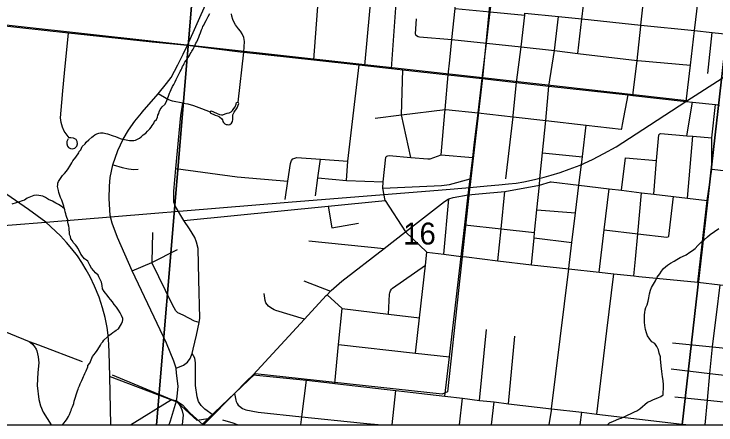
# Model space of a CAD drawing. Extents: x 0 to 34, y -3.9 to 26.2.
# Drawn here: x 5.335 to 6.675, y 14.1 to 14.885 of the extents above; entities that cross this region are included whole.
import ezdxf

# ---------------------------------------------------------------- set-up
doc = ezdxf.new("R2010")
doc.units = 0
for name, color, linetype in [('GM_X_City_Street', 7, 'Continuous'), ('GM_X_County_Road', 7, 'Continuous'), ('GM_X_Interchange_Ramps', 7, 'Continuous'), ('GM_X_Interstate_Route', 7, 'Continuous'), ('GM_X_Minor_River', 7, 'Continuous'), ('GM_X_Rail_Line', 7, 'Continuous'), ('GM_X_Section_Text', 7, 'Continuous'), ('GM_X_State_Shield', 7, 'Continuous'), ('GM_X_Township_Road', 7, 'Continuous')]:
    doc.layers.add(name, color=color, linetype=linetype)

msp = doc.modelspace()

# ---------------------------------------------------------------- linework, layer by layer
at = {"layer": 'GM_X_City_Street'}
for p, q in [((5.907, 14.7972), (5.9228, 15.002)), ((6.6592, 14.7711), (6.6674, 14.8497)), ((5.7629, 14.7169), (5.7738, 14.8119)), ((6.6189, 14.6524), (6.6302, 14.7168)), ((6.6202, 14.5332), (6.6307, 14.6515)), ((6.3437, 14.62), (6.4197, 14.612)), ((6.4946, 14.5483), (6.5021, 14.6104)), ((6.5021, 14.6104), (6.5613, 14.6049)), ((6.1551, 14.4261), (6.1651, 14.5317)), ((5.9343, 14.5181), (5.9418, 14.4763)), ((6.3329, 14.5108), (6.4067, 14.5054)), ((5.9418, 14.4763), (5.9922, 14.4856)), ((6.3276, 14.4576), (6.3998, 14.4486)), ((5.8976, 14.452), (6.0415, 14.4373)), ((5.8881, 14.3755), (5.939, 14.3554)), ((6.2233, 14.147), (6.2369, 14.2823)), ((6.2784, 14.1406), (6.2908, 14.2694)), ((5.6748, 14.2366), (5.6767, 14.2446)), ((6.0567, 14.1), (6.0636, 14.1661)), ((5.5575, 14.1), (5.6352, 14.1489)), ((6.1854, 14.1), (6.1912, 14.1514)), ((6.4153, 14.1), (6.4185, 14.1246)), ((6.6098, 14.1), (6.61, 14.1017))]:
    msp.add_line(p, q, dxfattribs=at)
for points in [[(6.15, 14.6163), (6.1575, 14.6966), (6.1581, 14.7026), (6.1635, 14.7688), (6.167, 14.797), (6.1707, 14.8362), (6.1767, 14.8958), (6.1769, 14.8976), (6.184, 14.968), (6.1848, 14.9759), (6.1993, 15.1189), (6.2028, 15.1537), (6.2075, 15.1994)], [(6.4111, 14.8098), (6.4188, 14.8758), (6.4194, 14.8804), (6.4271, 14.947), (6.4333, 15.0223), (6.4383, 15.083)], [(6.0554, 14.7812), (6.0641, 14.9056), (6.0652, 14.9071), (6.0667, 14.9078), (6.0698, 14.9081), (6.0804, 14.9086), (6.0825, 14.909), (6.0838, 14.9101), (6.0846, 14.9112), (6.0851, 14.9138), (6.094, 14.9866), (6.0979, 15.0186), (6.1013, 15.0467)], [(6.5161, 14.7291), (6.5244, 14.7965), (6.5312, 14.8617), (6.5315, 14.864), (6.5388, 14.9335)], [(5.7738, 14.8119), (5.7749, 14.8322), (5.7735, 14.8402), (5.7706, 14.8469), (5.7674, 14.852), (5.7636, 14.8565), (5.7577, 14.8645), (5.7539, 14.8712), (5.7526, 14.8747), (5.7509, 14.8808), (5.75, 14.8853)], [(6.1767, 14.8958), (6.2437, 14.8894), (6.3098, 14.883), (6.3102, 14.8869), (6.3742, 14.8805), (6.4188, 14.8758), (6.5315, 14.864), (6.6338, 14.8532), (6.6674, 14.8497), (6.7211, 14.844), (6.785, 14.8373)], [(6.1022, 14.8756), (6.1007, 14.8472), (6.1009, 14.8462), (6.1014, 14.8453), (6.1031, 14.8438), (6.1062, 14.8423), (6.1086, 14.8416), (6.1707, 14.8362)], [(6.2737, 14.5701), (6.2874, 14.6884), (6.2877, 14.6912), (6.2942, 14.7541), (6.3028, 14.8225), (6.3098, 14.883)], [(6.3225, 14.4061), (6.3276, 14.4576), (6.3286, 14.4675), (6.3329, 14.5108), (6.3376, 14.5581), (6.3388, 14.571), (6.3437, 14.62), (6.3498, 14.6813), (6.3558, 14.7469), (6.3662, 14.8151), (6.3742, 14.8805)], [(5.4381, 14.6468), (5.4358, 14.6417), (5.4355, 14.6371), (5.4367, 14.6328), (5.439, 14.6299), (5.443, 14.6282), (5.4461, 14.6276), (5.451, 14.629), (5.4547, 14.6328), (5.4561, 14.6371), (5.4556, 14.6414), (5.4533, 14.6454), (5.4484, 14.648), (5.4432, 14.6486), (5.4404, 14.6486), (5.4344, 14.656), (5.4304, 14.6612), (5.4272, 14.6686), (5.4246, 14.6778), (5.4235, 14.6864), (5.4261, 14.7159), (5.4281, 14.7385), (5.4312, 14.7717), (5.4391, 14.8493)], [(6.1707, 14.8362), (6.2366, 14.8294), (6.3028, 14.8225), (6.3662, 14.8151), (6.4111, 14.8098), (6.5244, 14.7965), (6.5258, 14.7963), (6.6258, 14.7871)], [(5.9694, 14.5669), (5.9723, 14.6037), (5.9936, 14.788)], [(6.092, 14.6112), (6.0747, 14.6922), (6.077, 14.7786)], [(5.6569, 14.7149), (5.6373, 14.7186), (5.6284, 14.722), (5.6221, 14.7257), (5.6103, 14.7327)], [(6.4952, 14.6661), (6.4965, 14.674), (6.5072, 14.7303)], [(5.6767, 14.2446), (5.6831, 14.2717), (5.6885, 14.2955), (5.6897, 14.304), (5.6874, 14.3776), (5.6865, 14.4371), (5.6835, 14.4495), (5.6798, 14.4581), (5.67, 14.4746), (5.6589, 14.4903), (5.6433, 14.517), (5.6401, 14.5257), (5.6399, 14.5348), (5.6401, 14.5464), (5.6438, 14.59), (5.6533, 14.6914), (5.6569, 14.7149)], [(5.6569, 14.7149), (5.6666, 14.7136), (5.6772, 14.7105), (5.6925, 14.7043), (5.709, 14.6984)], [(5.709, 14.6984), (5.7093, 14.696), (5.7188, 14.692), (5.7233, 14.6903), (5.7271, 14.6885), (5.7313, 14.6847), (5.7331, 14.6827), (5.7335, 14.6798), (5.735, 14.678), (5.7371, 14.6754), (5.74, 14.674), (5.7421, 14.6737), (5.7448, 14.6735), (5.7471, 14.6741), (5.7499, 14.6766), (5.752, 14.6798), (5.7528, 14.6833), (5.7526, 14.6872), (5.7525, 14.6893), (5.7528, 14.6922), (5.7536, 14.6949), (5.7552, 14.6977), (5.7607, 14.7059), (5.7637, 14.7142), (5.7629, 14.7169)], [(5.709, 14.6984), (5.7109, 14.6998), (5.7212, 14.6957), (5.7274, 14.6931), (5.7308, 14.6925), (5.7336, 14.6925), (5.7381, 14.6941), (5.742, 14.6954), (5.7458, 14.6963), (5.7494, 14.6983), (5.752, 14.7009), (5.7546, 14.7043), (5.7567, 14.7079), (5.7589, 14.7131), (5.7596, 14.7158), (5.7629, 14.7169)], [(6.6401, 14.3725), (6.6576, 14.5287), (6.6668, 14.5885), (6.6667, 14.6485), (6.6738, 14.7119)], [(6.0242, 14.6858), (6.0747, 14.6922), (6.1581, 14.7026), (6.159, 14.7027), (6.2207, 14.696), (6.2874, 14.6884), (6.3498, 14.6813), (6.4271, 14.6725), (6.4936, 14.665), (6.4946, 14.6652), (6.4952, 14.6661)], [(6.3566, 14.1), (6.3605, 14.1275), (6.361, 14.1311), (6.3936, 14.3981), (6.3944, 14.405), (6.3998, 14.4486), (6.4067, 14.5054), (6.4131, 14.5581), (6.4197, 14.612), (6.4199, 14.6131), (6.4271, 14.6725)], [(6.5558, 14.5409), (6.5613, 14.6049), (6.5655, 14.6539), (6.5662, 14.655), (6.5673, 14.6558), (6.5697, 14.6565)], [(6.5697, 14.6565), (6.6189, 14.6524), (6.6307, 14.6515), (6.6667, 14.6485)], [(5.8523, 14.5305), (5.8577, 14.5658), (5.8628, 14.5993), (5.8648, 14.605), (5.8672, 14.6083)], [(5.8672, 14.6083), (5.8748, 14.6108), (5.9196, 14.6075), (5.9723, 14.6037)], [(5.9106, 14.538), (5.915, 14.572), (5.9196, 14.6075)], [(6.0396, 14.5643), (6.0443, 14.6114), (6.0449, 14.6125), (6.0462, 14.6135), (6.0482, 14.6144), (6.0509, 14.6148), (6.092, 14.6112), (6.125, 14.6084), (6.1292, 14.6083), (6.15, 14.6163), (6.2105, 14.6106)], [(5.5239, 14.597), (5.5416, 14.5917), (5.5534, 14.5893), (5.5635, 14.5881), (5.5718, 14.5889)], [(5.6438, 14.59), (5.7607, 14.5739), (5.8577, 14.5658)], [(6.6668, 14.5885), (6.6948, 14.5856), (6.7429, 14.5805)], [(5.915, 14.572), (5.9694, 14.5669), (6.0396, 14.5643)], [(6.039, 14.5525), (6.1507, 14.5572), (6.1663, 14.5594), (6.2056, 14.5702)], [(6.0431, 14.529), (6.039, 14.5525), (6.0396, 14.5643)], [(6.2019, 14.5397), (6.2219, 14.5415), (6.272, 14.5458), (6.3376, 14.5581), (6.359, 14.5644), (6.3603, 14.5644), (6.4131, 14.5581), (6.4708, 14.5511), (6.4946, 14.5483), (6.5325, 14.5437), (6.5558, 14.5409), (6.5937, 14.5364), (6.6202, 14.5332), (6.6576, 14.5287)], [(6.4517, 14.3916), (6.4614, 14.4728), (6.4708, 14.5511)], [(6.2584, 14.4137), (6.2646, 14.4744), (6.272, 14.5458)], [(6.5178, 14.3849), (6.5208, 14.4167), (6.5253, 14.4654), (6.5325, 14.5437)], [(5.6589, 14.4903), (5.9343, 14.5181), (6.0431, 14.529)], [(6.0431, 14.529), (6.0822, 14.4689), (6.1231, 14.4299), (6.1551, 14.4261), (6.1883, 14.4221), (6.1983, 14.4209)], [(6.5811, 14.4589), (6.5837, 14.4593), (6.5843, 14.4598), (6.5848, 14.4606), (6.5937, 14.5364)], [(6.1952, 14.482), (6.2646, 14.4744), (6.3286, 14.4675)], [(6.4614, 14.4728), (6.5253, 14.4654), (6.5811, 14.4589)], [(5.6885, 14.2955), (5.6792, 14.2982), (5.6577, 14.31), (5.6478, 14.3144), (5.6435, 14.3178), (5.6376, 14.3294), (5.5981, 14.4104), (5.5983, 14.4112), (5.5999, 14.4676)], [(5.5604, 14.3947), (5.5981, 14.4104), (5.6467, 14.4353)], [(6.1014, 14.2373), (6.109, 14.3046), (6.1203, 14.4053), (6.1231, 14.4299)], [(6.1983, 14.4209), (6.2584, 14.4137), (6.3225, 14.4061), (6.3936, 14.3981), (6.4517, 14.3916), (6.48, 14.3887), (6.5178, 14.3849), (6.5272, 14.3839)], [(6.0496, 14.3117), (6.0514, 14.3499), (6.0519, 14.3524), (6.0532, 14.3561), (6.0552, 14.3594), (6.057, 14.3615), (6.1203, 14.4053)], [(6.447, 14.1207), (6.4666, 14.2796), (6.48, 14.3887)], [(6.5272, 14.3839), (6.6401, 14.3725), (6.6828, 14.3678), (6.7247, 14.3632), (6.786, 14.3565), (6.8896, 14.3452), (6.9691, 14.3396)], [(6.6541, 14.1), (6.6585, 14.1472), (6.6633, 14.1985), (6.6681, 14.2492), (6.6682, 14.2501), (6.6756, 14.3102), (6.6828, 14.3678)], [(5.8894, 14.3021), (5.8345, 14.3188), (5.8312, 14.32), (5.8249, 14.324), (5.8209, 14.3267), (5.8178, 14.3299), (5.8156, 14.3333), (5.8142, 14.3376), (5.8123, 14.3513)], [(5.9324, 14.3485), (5.9611, 14.3223), (6.0496, 14.3117), (6.109, 14.3046)], [(5.947, 14.1795), (5.9544, 14.2537), (5.9611, 14.3223)], [(5.364, 14.2594), (5.3816, 14.2528), (5.4649, 14.2211)], [(5.9544, 14.2537), (6.1014, 14.2373), (6.1661, 14.2301)], [(5.6442, 14.2083), (5.6581, 14.2143), (5.6661, 14.2201), (5.6711, 14.2267), (5.6748, 14.2366)], [(5.7152, 14.119), (5.6994, 14.1305), (5.692, 14.137), (5.6871, 14.1451), (5.6846, 14.1539), (5.6811, 14.1751), (5.6811, 14.1966), (5.6811, 14.219), (5.6801, 14.2277), (5.6748, 14.2366)], [(6.589, 14.207), (6.6633, 14.1985), (6.7681, 14.1865), (6.8539, 14.1767), (6.9152, 14.1703), (7.0421, 14.1569), (7.1738, 14.1431), (7.242, 14.1382), (7.2931, 14.1334)], [(5.5223, 14.1956), (5.6352, 14.1489), (5.6448, 14.1459)], [(5.8826, 14.1), (5.8845, 14.1158), (5.8929, 14.1853)], [(5.7556, 14.16), (5.758, 14.1474), (5.7588, 14.1448), (5.7606, 14.1411), (5.763, 14.1381), (5.7651, 14.136), (5.771, 14.1315), (5.7771, 14.1288), (5.8009, 14.1244), (5.8845, 14.1158), (5.9959, 14.1043)], [(6.5959, 14.1536), (6.6585, 14.1472), (6.7615, 14.1365), (6.9227, 14.1199)], [(5.6448, 14.1459), (5.6565, 14.1386), (5.6703, 14.1232), (5.6958, 14.1)], [(5.6448, 14.1459), (5.6501, 14.1393), (5.6531, 14.1341), (5.656, 14.1272), (5.6575, 14.1187), (5.6563, 14.1072), (5.6556, 14.1)], [(5.7612, 14.1), (5.7531, 14.1032), (5.7337, 14.1091)], [(5.9959, 14.1043), (6.0081, 14.1031), (6.0377, 14.1)]]:
    msp.add_lwpolyline(points, dxfattribs=at)
at = {"layer": 'GM_X_County_Road'}
for p, q in [((5.5985, 14.832), (5.6661, 14.8253)), ((5.6661, 14.8253), (5.7668, 14.8128)), ((5.5716, 14.6879), (5.5779, 14.6954)), ((6.2465, 14.1), (6.2511, 14.1445))]:
    msp.add_line(p, q, dxfattribs=at)
for points in [[(6.0048, 14.7868), (6.0233, 14.9949), (6.0314, 15.0714), (6.042, 15.1707), (6.046, 15.2084)], [(5.6661, 14.8253), (5.7213, 14.9502), (5.7334, 14.9768)], [(6.1574, 14.1553), (6.1661, 14.2301), (6.1883, 14.4221), (6.1952, 14.482), (6.2019, 14.5397), (6.2056, 14.5702), (6.2105, 14.6106), (6.2134, 14.6347), (6.2207, 14.696), (6.2287, 14.7616), (6.2366, 14.8294), (6.2437, 14.8894), (6.2517, 14.958)], [(6.618, 14.7181), (6.6258, 14.7871), (6.6338, 14.8532), (6.6409, 14.9114)], [(4.9965, 14.7949), (5.1396, 14.8641), (5.168, 14.8759), (5.1749, 14.8773), (5.1826, 14.8773), (5.1904, 14.8766), (5.2249, 14.8735), (5.2943, 14.8649), (5.2987, 14.8646), (5.4391, 14.8493), (5.5927, 14.8325), (5.5985, 14.832)], [(5.5779, 14.6954), (5.5798, 14.6977), (5.6103, 14.7327), (5.626, 14.7521), (5.6347, 14.7639), (5.6473, 14.7876), (5.6575, 14.8082), (5.6661, 14.8253)], [(5.7668, 14.8128), (5.7738, 14.8119), (5.907, 14.7972), (5.9936, 14.788), (6.0048, 14.7868), (6.0554, 14.7812), (6.077, 14.7786), (6.1635, 14.7688), (6.2287, 14.7616), (6.2942, 14.7541), (6.3558, 14.7469), (6.5072, 14.7303), (6.5161, 14.7291), (6.618, 14.7181), (6.6302, 14.7168), (6.6738, 14.7119), (6.6816, 14.711)], [(5.6335, 14.108), (5.6448, 14.1459), (5.646, 14.1545), (5.6483, 14.1742), (5.645, 14.199), (5.6442, 14.2083), (5.6397, 14.2219), (5.6259, 14.2564), (5.5604, 14.3947), (5.5326, 14.4583), (5.5222, 14.4855), (5.5182, 14.4999), (5.5162, 14.5327), (5.5174, 14.5561), (5.5187, 14.573), (5.5236, 14.5971), (5.5332, 14.6245), (5.5431, 14.6462), (5.5536, 14.6631), (5.5654, 14.6803), (5.5716, 14.6879)], [(5.7792, 14.184), (5.7911, 14.196), (5.8894, 14.3021), (5.931, 14.3471), (5.9324, 14.3485), (5.939, 14.3554), (5.9403, 14.3568), (5.9608, 14.3746), (6.0415, 14.4373), (6.0822, 14.4689), (6.1566, 14.5268), (6.1635, 14.5312), (6.1651, 14.5317), (6.1734, 14.5344), (6.2019, 14.5397)], [(5.2207, 14.318), (5.364, 14.2594), (5.3704, 14.2544), (5.3754, 14.2481), (5.3762, 14.2465), (5.3769, 14.2449)], [(5.3769, 14.2449), (5.3785, 14.2417), (5.3809, 14.2302), (5.3822, 14.2184), (5.3804, 14.2002), (5.3788, 14.1755), (5.3824, 14.1485), (5.3855, 14.1363), (5.3907, 14.1244), (5.4056, 14.1)], [(5.7911, 14.196), (5.8929, 14.1853), (5.9426, 14.18), (5.947, 14.1795), (6.0636, 14.1661), (6.1574, 14.1553), (6.1912, 14.1514), (6.2233, 14.147), (6.2511, 14.1445), (6.2784, 14.1406), (6.361, 14.1311), (6.4185, 14.1246), (6.447, 14.1207), (6.61, 14.1017), (6.6242, 14.1)], [(5.6965, 14.1), (5.703, 14.1065), (5.7556, 14.16), (5.7792, 14.184)], [(5.6306, 14.1), (5.6323, 14.1042), (5.6335, 14.108)]]:
    msp.add_lwpolyline(points, dxfattribs=at)
at = {"layer": 'GM_X_Interchange_Ramps'}
msp.add_lwpolyline([(3.5682, 14.1), (7.2913, 14.1)], dxfattribs=at)
at = {"layer": 'GM_X_Interstate_Route'}
msp.add_lwpolyline([(2.5468, 14.1), (8.9, 14.1)], dxfattribs=at)
at = {"layer": 'GM_X_Minor_River'}
for points in [[(5.6669, 14.8016), (5.6689, 14.8046), (5.6713, 14.8087), (5.673, 14.8116), (5.6746, 14.8142), (5.6766, 14.818), (5.6791, 14.8232), (5.6804, 14.8262), (5.682, 14.8291), (5.6836, 14.8317), (5.6874, 14.8407), (5.6891, 14.8444), (5.6908, 14.8493), (5.6925, 14.8545), (5.6946, 14.8583), (5.6954, 14.8609), (5.6971, 14.8635), (5.6987, 14.8668), (5.7016, 14.8724), (5.7053, 14.8802), (5.7086, 14.8858)], [(5.4395, 14.48), (5.4385, 14.4842), (5.4379, 14.4872), (5.4373, 14.4918), (5.4356, 14.4965), (5.4346, 14.5003), (5.4336, 14.5034), (5.4326, 14.5069), (5.4316, 14.5111), (5.4306, 14.5149), (5.43, 14.518), (5.429, 14.5215), (5.4276, 14.5253), (5.4259, 14.5292), (5.4238, 14.5346), (5.4224, 14.5385), (5.4207, 14.5442), (5.4198, 14.5481), (5.4188, 14.5527), (5.4181, 14.5554), (5.4183, 14.5588), (5.4188, 14.5618), (5.42, 14.5648), (5.4249, 14.5729), (5.4277, 14.5763), (5.4313, 14.5803), (5.4349, 14.5851), (5.4381, 14.5895), (5.4417, 14.5943), (5.4454, 14.6006), (5.4471, 14.6047), (5.4527, 14.6117), (5.4583, 14.6198), (5.4592, 14.6225), (5.4623, 14.6258), (5.4649, 14.6317), (5.4708, 14.6372), (5.4724, 14.6402), (5.4779, 14.6445), (5.4834, 14.6496), (5.4862, 14.6518), (5.4893, 14.6543), (5.4932, 14.6564), (5.4966, 14.6574), (5.5001, 14.658), (5.505, 14.6578), (5.5099, 14.6569), (5.5133, 14.6559), (5.5171, 14.655), (5.5204, 14.6534), (5.5242, 14.6521), (5.5283, 14.6508), (5.5373, 14.6474), (5.5414, 14.646), (5.5456, 14.6451), (5.549, 14.6446), (5.552, 14.6441), (5.5554, 14.6432), (5.5637, 14.6436), (5.5668, 14.6442), (5.5703, 14.646), (5.5742, 14.6481), (5.5773, 14.6502), (5.5816, 14.6539), (5.5863, 14.6575), (5.5899, 14.6611), (5.5939, 14.6655), (5.5967, 14.6688), (5.5987, 14.6718), (5.6023, 14.6773), (5.6032, 14.68), (5.6071, 14.6832), (5.6088, 14.6881), (5.6097, 14.6915), (5.611, 14.6952), (5.6119, 14.6982), (5.6139, 14.7023), (5.6159, 14.7049), (5.6176, 14.7075), (5.6235, 14.713), (5.6268, 14.7197), (5.628, 14.7227), (5.6306, 14.7301), (5.6315, 14.7339), (5.6328, 14.7365), (5.6348, 14.7406), (5.6374, 14.7466), (5.6398, 14.7503), (5.6423, 14.7555), (5.6443, 14.7596), (5.6468, 14.7652), (5.6518, 14.7749), (5.6538, 14.7786), (5.6551, 14.7812), (5.6567, 14.7846), (5.6583, 14.7875), (5.6596, 14.7902), (5.6612, 14.7931), (5.6632, 14.7961), (5.6652, 14.7987), (5.6669, 14.8016)], [(5.4311, 14.5131), (5.4247, 14.5182), (5.4198, 14.5211), (5.415, 14.5236), (5.4083, 14.5273), (5.4008, 14.531), (5.3949, 14.5343), (5.39, 14.5368), (5.3787, 14.5391), (5.373, 14.5386), (5.3661, 14.5355), (5.3599, 14.5334), (5.3548, 14.5295), (5.3502, 14.5282), (5.3436, 14.5258), (5.339, 14.5241), (5.3309, 14.5217)], [(5.4269, 14.1), (5.4272, 14.1003), (5.4307, 14.104), (5.4328, 14.1065), (5.4348, 14.1095), (5.4368, 14.1132), (5.4388, 14.1162), (5.4405, 14.1199), (5.4426, 14.1248), (5.4438, 14.1277), (5.4443, 14.1308), (5.4468, 14.1348), (5.4477, 14.1378), (5.4489, 14.1412), (5.4499, 14.1454), (5.4508, 14.1491), (5.4547, 14.1615), (5.456, 14.1653), (5.4572, 14.1682), (5.4581, 14.1712), (5.4598, 14.1746), (5.4614, 14.1783), (5.4627, 14.1813), (5.4643, 14.1851), (5.466, 14.1892), (5.4677, 14.1925), (5.4685, 14.1951), (5.4702, 14.1985), (5.4723, 14.2034), (5.4756, 14.2108), (5.4761, 14.2138), (5.4793, 14.2183), (5.4823, 14.2246), (5.4848, 14.2306), (5.488, 14.2343), (5.49, 14.2372), (5.4924, 14.2405), (5.4948, 14.2442), (5.4997, 14.2524), (5.5021, 14.2561), (5.5041, 14.2587), (5.5065, 14.262), (5.5132, 14.2682), (5.516, 14.2711), (5.5203, 14.2744), (5.5238, 14.2769), (5.5273, 14.279), (5.5301, 14.2808), (5.534, 14.2837), (5.5364, 14.287), (5.5401, 14.2933), (5.5418, 14.2978), (5.5426, 14.3008), (5.5424, 14.3035), (5.5399, 14.3093), (5.5375, 14.3143), (5.5342, 14.3194), (5.5303, 14.3249), (5.5263, 14.33), (5.5227, 14.3351), (5.5191, 14.3394), (5.5158, 14.3433), (5.5126, 14.348), (5.5093, 14.352), (5.5068, 14.3551), (5.5039, 14.3602), (5.5034, 14.3663), (5.5018, 14.3728), (5.5, 14.3767), (5.4979, 14.3802), (5.4965, 14.3829), (5.4955, 14.386), (5.4903, 14.3908), (5.4871, 14.3947), (5.4831, 14.3998), (5.4795, 14.4053), (5.4756, 14.4127), (5.473, 14.4147), (5.4697, 14.4171), (5.4668, 14.4207), (5.4625, 14.4262), (5.4593, 14.4331), (5.4565, 14.4378), (5.4547, 14.4406), (5.4521, 14.4441), (5.4478, 14.4488), (5.4467, 14.4515), (5.4435, 14.4555), (5.4425, 14.4597), (5.4411, 14.4639), (5.4409, 14.4681), (5.4403, 14.4727), (5.4401, 14.4761), (5.4395, 14.48)], [(6.5402, 14.2825), (6.539, 14.2898), (6.5385, 14.2963), (6.5384, 14.3047), (6.5383, 14.3104), (6.5388, 14.3149), (6.5394, 14.3198), (6.5407, 14.3243), (6.5432, 14.3295), (6.545, 14.3367), (6.5468, 14.3431), (6.5478, 14.3503), (6.5496, 14.3574), (6.5514, 14.3623), (6.5595, 14.3753), (6.5624, 14.3824), (6.5676, 14.3886), (6.5708, 14.3938), (6.5748, 14.3986), (6.5823, 14.4051), (6.5882, 14.409), (6.5948, 14.4129), (6.6002, 14.4158), (6.6064, 14.4197), (6.6111, 14.4218), (6.6177, 14.4253), (6.6251, 14.4303), (6.6298, 14.4332), (6.6349, 14.4371), (6.6404, 14.4426), (6.6467, 14.4492), (6.6522, 14.4539), (6.6585, 14.4593), (6.6637, 14.4637), (6.6801, 14.4752)], [(6.4678, 14.1), (6.4716, 14.104), (6.4794, 14.1071), (6.4894, 14.1117), (6.494, 14.113), (6.4994, 14.1154), (6.5056, 14.1186), (6.5126, 14.1217), (6.5192, 14.1249), (6.5239, 14.1273), (6.5293, 14.1309), (6.5344, 14.1353), (6.5391, 14.1392), (6.5443, 14.1436), (6.5489, 14.1457), (6.5539, 14.1481), (6.5586, 14.1498), (6.564, 14.1519), (6.5694, 14.1543), (6.5741, 14.1576), (6.5739, 14.1625), (6.5745, 14.1693), (6.5748, 14.1765), (6.574, 14.1849), (6.5728, 14.1918), (6.5722, 14.1972), (6.5713, 14.2022), (6.5702, 14.2129), (6.5693, 14.2197), (6.5688, 14.2255), (6.5686, 14.2304), (6.5666, 14.2373), (6.5649, 14.2435), (6.5621, 14.2501), (6.5578, 14.2556), (6.5526, 14.2588), (6.5486, 14.2636), (6.5439, 14.2702), (6.5419, 14.276), (6.5402, 14.2825)]]:
    msp.add_lwpolyline(points, dxfattribs=at)
at = {"layer": 'GM_X_Rail_Line'}
for p, q in [((6.2289, 14.7633), (6.2046, 14.5541)), ((6.6192, 14.7194), (6.2289, 14.7633)), ((6.2046, 14.5541), (6.2042, 14.5505)), ((5.6934, 14.1), (5.7048, 14.1116))]:
    msp.add_line(p, q, dxfattribs=at)
for points in [[(6.2289, 14.7633), (5.2156, 14.8749), (5.1802, 14.8803), (5.1463, 14.9113), (5.0528, 15.0986), (5.0219, 15.1327), (4.9732, 15.1579), (4.9307, 15.1641), (4.8773, 15.172), (4.7485, 15.183), (4.6967, 15.1626), (4.67, 15.1311), (4.6682, 15.129)], [(6.7886, 14.9093), (6.249, 14.9675), (6.2289, 14.7633)], [(5.2664, 14.4774), (5.3957, 14.4877), (5.858, 14.5253), (6.1522, 14.5489), (6.2051, 14.5536), (6.2377, 14.5565), (6.2605, 14.5585), (6.2789, 14.5603), (6.2935, 14.5621), (6.3078, 14.5645), (6.3283, 14.5687), (6.3467, 14.5731), (6.3603, 14.5769), (6.3773, 14.5822), (6.3943, 14.5884), (6.4154, 14.5964), (6.4391, 14.6071), (6.4607, 14.6183), (6.4843, 14.6316), (6.548, 14.6727), (6.6194, 14.7189), (6.7609, 14.8099)], [(5.5199, 14.1), (5.5175, 14.1928), (5.5164, 14.2393), (5.5159, 14.2536), (5.5147, 14.2718), (5.5128, 14.2859), (5.5087, 14.3053), (5.504, 14.3237), (5.4973, 14.3441), (5.4888, 14.3654), (5.4802, 14.3832), (5.4728, 14.3965), (5.4644, 14.4101), (5.4558, 14.4231), (5.4455, 14.4367), (5.4353, 14.4487), (5.4235, 14.4616), (5.3957, 14.4877), (5.3625, 14.5113), (5.2482, 14.5904)], [(6.2042, 14.5505), (6.1623, 14.1634), (6.1523, 14.1591), (5.7949, 14.1978), (5.7048, 14.1116)], [(5.7048, 14.1116), (5.6843, 14.1086), (5.6464, 14.1433), (5.5173, 14.1929)]]:
    msp.add_lwpolyline(points, dxfattribs=at)
at = {"layer": 'GM_X_State_Shield'}
for points in [[(4.9277, 14.1), (5.6066, 14.1), (5.6843, 15.0302), (4.6963, 15.1472), (4.5981, 14.1346)], [(5.6066, 14.1), (6.6105, 14.1), (6.7022, 14.9121), (5.6843, 15.0302)], [(6.6105, 14.1), (7.6139, 14.1), (7.6773, 14.7406), (6.7022, 14.9121)]]:
    msp.add_lwpolyline(points, close=True, dxfattribs=at)
at = {"layer": 'GM_X_Township_Road'}
msp.add_lwpolyline([(6.5919, 14.2568), (6.6681, 14.2492), (6.7736, 14.2387), (6.9068, 14.2267)], dxfattribs=at)

# ---------------------------------------------------------------- texts
at = {"layer": 'GM_X_Section_Text'}
msp.add_text('16', height=0.04186, rotation=0, dxfattribs=at).set_placement((6.0777, 14.4447))

doc.saveas('drawing.dxf')
